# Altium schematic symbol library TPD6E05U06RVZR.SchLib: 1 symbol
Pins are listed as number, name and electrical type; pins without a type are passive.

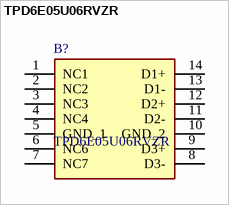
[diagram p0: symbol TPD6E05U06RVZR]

## TPD6E05U06RVZR
designator B?
6-Channel Ultra-Low-Capacitance IEC ESD Protection Diodes; Manufacturer_Name: Texas Instruments; Geometry.Height: 0.55mm
footprint SON50P135X350X55-14N
pins: 1 NC1, 2 NC2, 3 NC3, 4 NC4, 5 GND_1, 6 NC6, 7 NC7, 8 D3-, 9 D3+, 10 GND_2, 11 D2-, 12 D2+, 13 D1-, 14 D1+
